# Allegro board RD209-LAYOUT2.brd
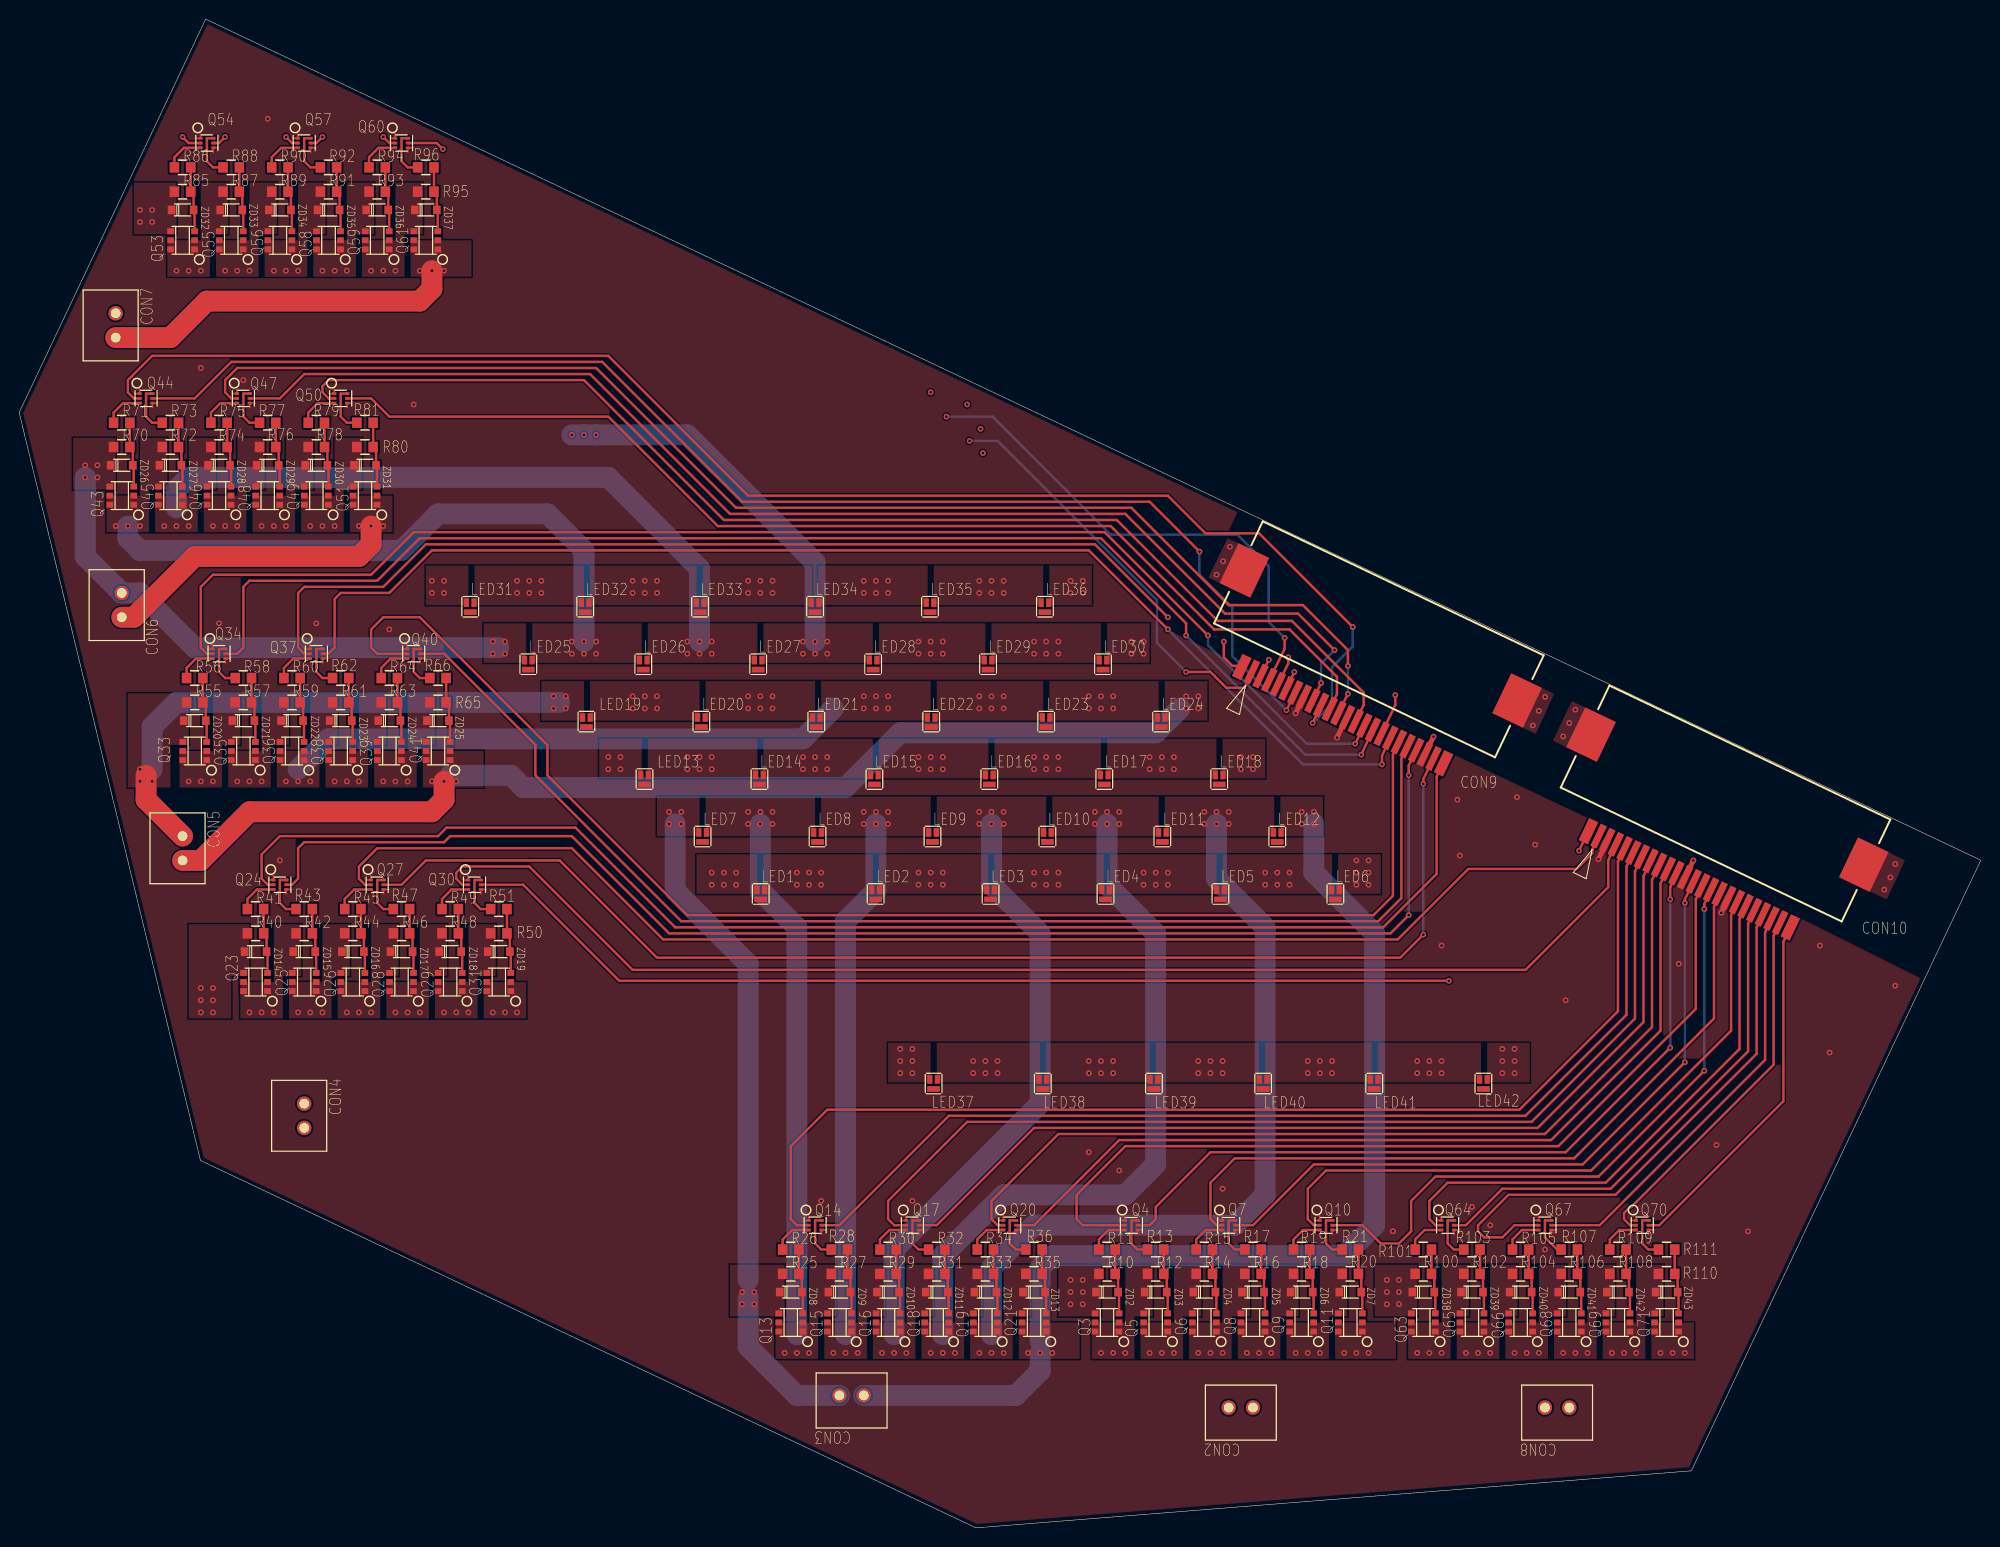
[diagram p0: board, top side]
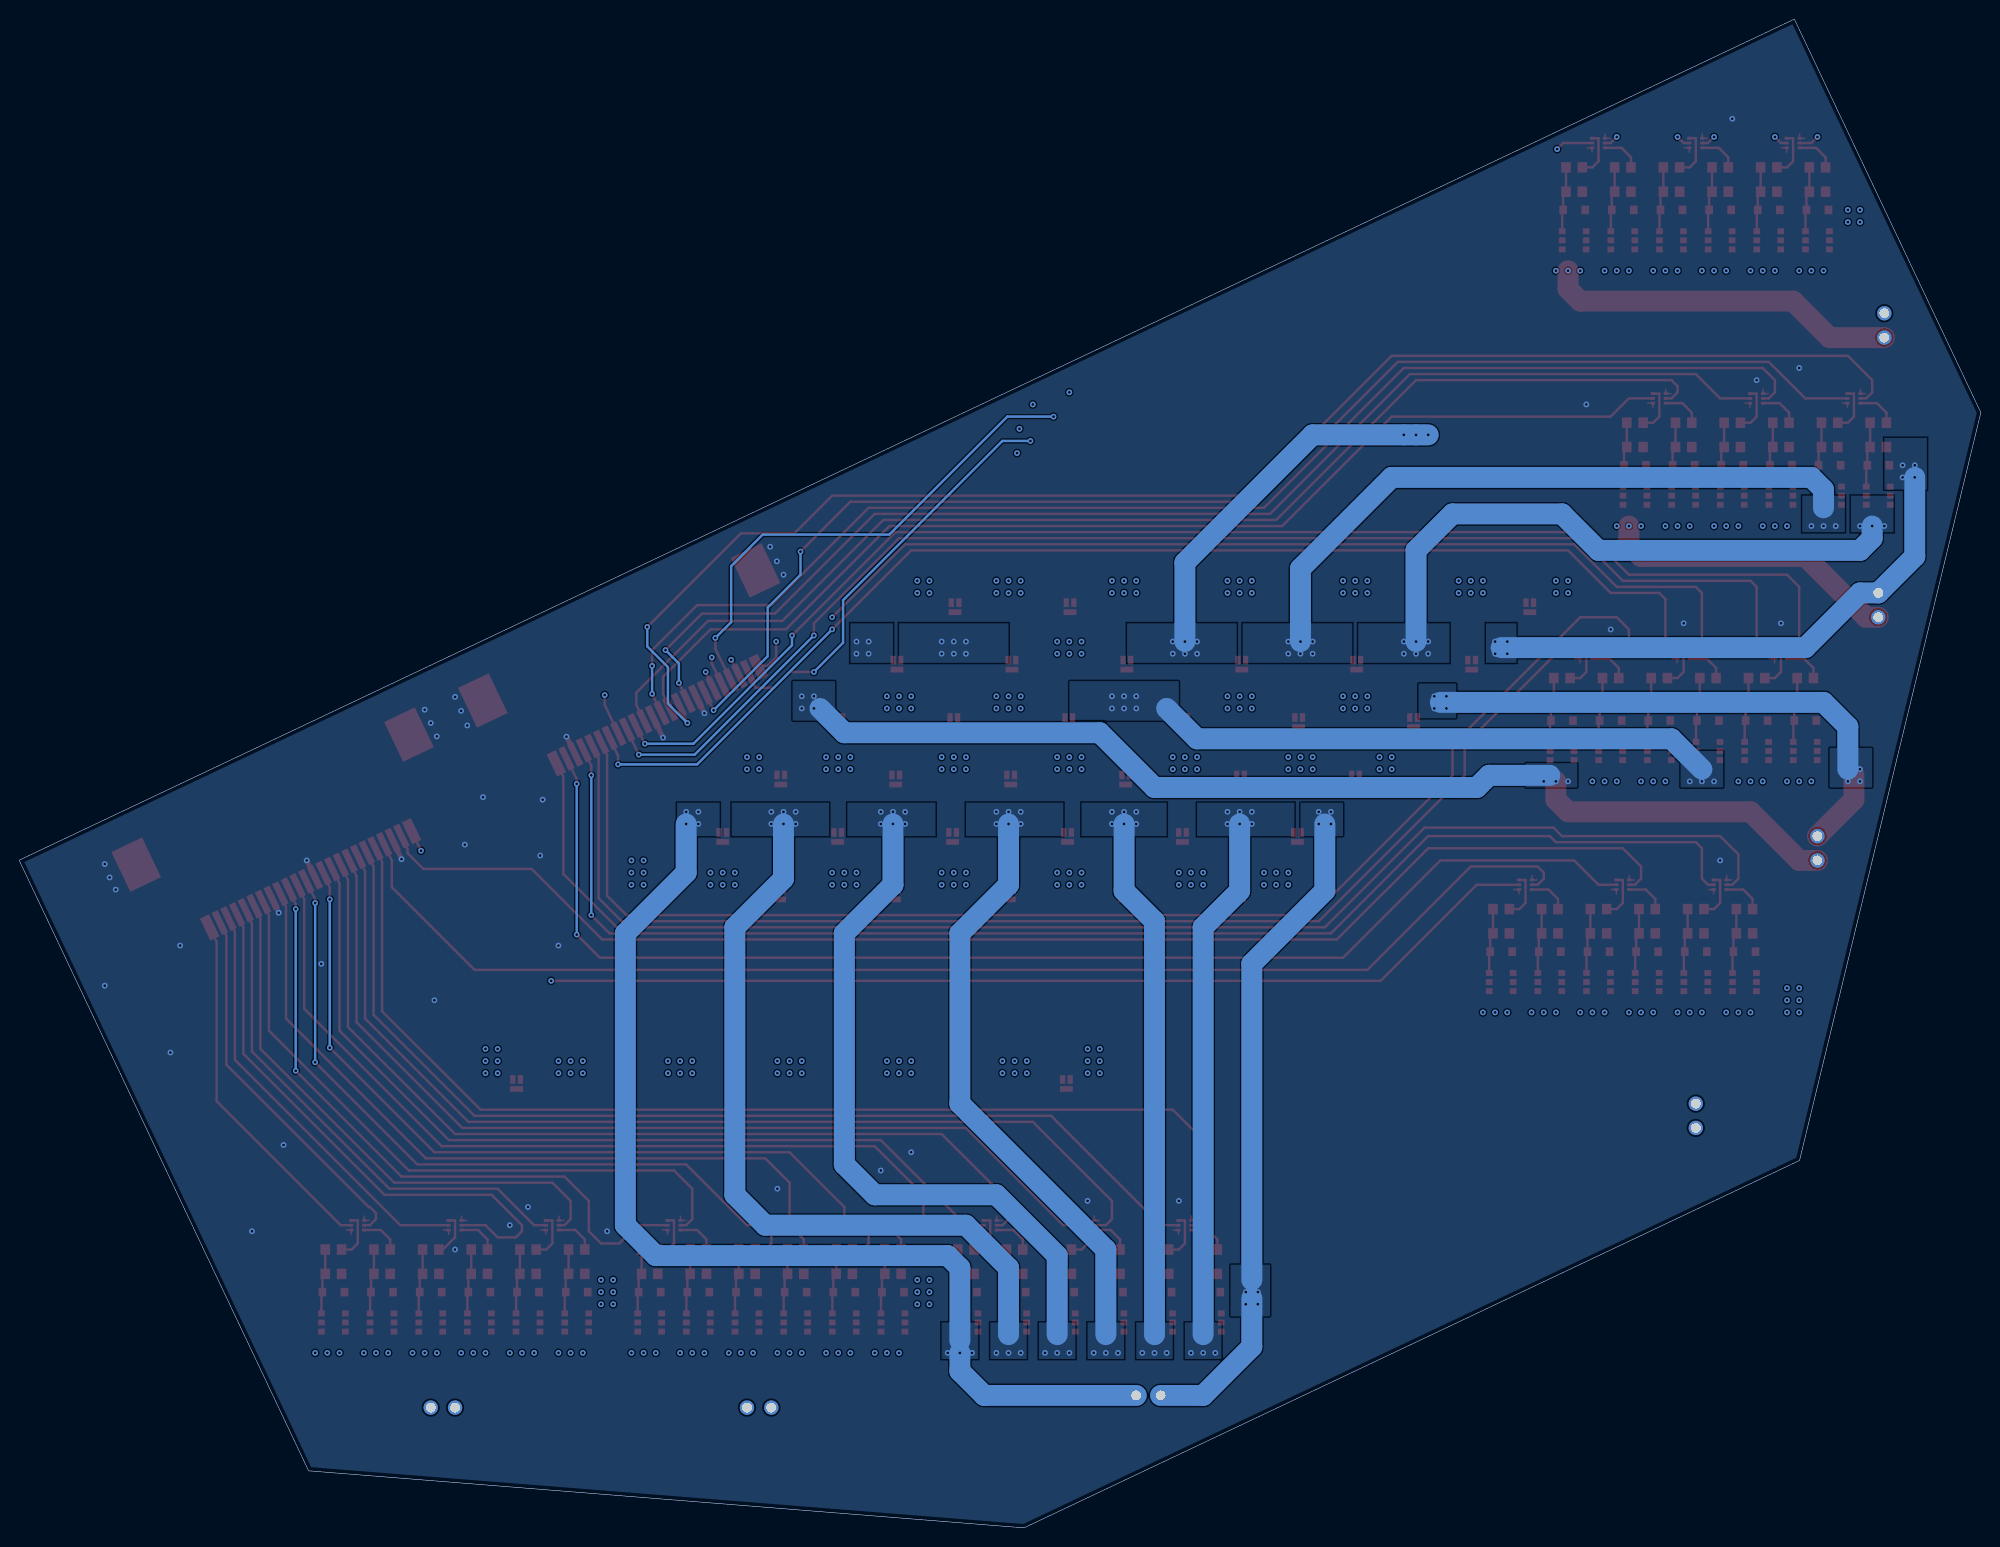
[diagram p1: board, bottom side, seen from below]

Outline 204.81 x 157.58 mm; copper layers: TOP, CONDUCTIVE2, CONDUCTIVE3, BOTTOM. Coordinates in mm from the lower left corner of the outline.
Outline path: 0,116.49 19.47,157.58 204.81,69.73 174.59,5.96 99.89,0 18.93,38.37 0,116.49

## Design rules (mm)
constraint set DEFAULT: 

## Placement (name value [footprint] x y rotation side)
CON2  -  [B2B_XH_A]  127.55 12.56 180 top
CON3  -  [B2B_XH_A]  86.91 13.83 180 top
CON4  -  [B2B_XH_A]  29.76 43.04 90 top
CON5  -  [B2B_XH_A]  17.06 70.98 90 top
CON6  -  [B2B_XH_A]  10.71 96.38 90 top
CON7  -  [B2B_XH_A]  10.07 125.59 90 top
CON8  -  [B2B_XH_A]  160.57 12.56 180 top
CON9  -  [WB01230AKP]  142.16 93.2 334.5 top
CON10  -  [WB01230AKP]  178.35 76.06 334.5 top
LED1  -  [KW]  77.42 66.21 0 top
LED2  -  [KW]  89.42 66.21 0 top
LED3  -  [KW]  101.42 66.21 0 top
LED4  -  [KW]  113.42 66.21 0 top
LED5  -  [KW]  125.42 66.21 0 top
LED6  -  [KW]  137.42 66.21 0 top
LED7  -  [KW]  71.35 72.21 0 top
LED8  -  [KW]  83.35 72.21 0 top
LED9  -  [KW]  95.35 72.21 0 top
LED10  -  [KW]  107.35 72.21 0 top
LED11  -  [KW]  119.35 72.21 0 top
LED12  -  [KW]  131.35 72.21 0 top
LED13  -  [KW]  65.29 78.21 0 top
LED14  -  [KW]  77.29 78.21 0 top
LED15  -  [KW]  89.29 78.21 0 top
LED16  -  [KW]  101.29 78.21 0 top
LED17  -  [KW]  113.29 78.21 0 top
LED18  -  [KW]  125.29 78.21 0 top
LED19  -  [KW]  59.22 84.21 0 top
LED20  -  [KW]  71.22 84.21 0 top
LED21  -  [KW]  83.22 84.21 0 top
LED22  -  [KW]  95.22 84.21 0 top
LED23  -  [KW]  107.22 84.21 0 top
LED24  -  [KW]  119.22 84.21 0 top
LED25  -  [KW]  53.16 90.21 0 top
LED26  -  [KW]  65.16 90.21 0 top
LED27  -  [KW]  77.16 90.21 0 top
LED28  -  [KW]  89.16 90.21 0 top
LED29  -  [KW]  101.16 90.21 0 top
LED30  -  [KW]  113.16 90.21 0 top
LED31  -  [KW]  47.09 96.21 0 top
LED32  -  [KW]  59.09 96.21 0 top
LED33  -  [KW]  71.09 96.21 0 top
LED34  -  [KW]  83.09 96.21 0 top
LED35  -  [KW]  95.09 96.21 0 top
LED36  -  [KW]  107.09 96.21 0 top
LED37  -  [KW]  95.47 46.41 0 top
LED38  -  [KW]  106.88 46.41 0 top
LED39  -  [KW]  118.47 46.41 0 top
LED40  -  [KW]  129.88 46.41 0 top
LED41  -  [KW]  141.47 46.41 0 top
LED42  -  [KW]  152.88 46.41 0 top
Q3  -  [TSOP6F]  113.58 21.45 90 top
Q4  -  [ES6]  116.12 31.61 270 top
Q5  -  [TSOP6F]  118.66 21.45 90 top
Q6  -  [TSOP6F]  123.74 21.45 90 top
Q7  -  [ES6]  126.28 31.61 270 top
Q8  -  [TSOP6F]  128.82 21.45 90 top
Q9  -  [TSOP6F]  133.9 21.45 90 top
Q10  -  [ES6]  136.44 31.61 270 top
Q11  -  [TSOP6F]  138.98 21.45 90 top
Q13  -  [TSOP6F]  80.56 21.45 90 top
Q14  -  [ES6]  83.1 31.61 270 top
Q15  -  [TSOP6F]  85.64 21.45 90 top
Q16  -  [TSOP6F]  90.72 21.45 90 top
Q17  -  [ES6]  93.26 31.61 270 top
Q18  -  [TSOP6F]  95.8 21.45 90 top
Q19  -  [TSOP6F]  100.88 21.45 90 top
Q20  -  [ES6]  103.42 31.61 270 top
Q21  -  [TSOP6F]  105.96 21.45 90 top
Q23  -  [TSOP6F]  24.68 57.01 90 top
Q24  -  [ES6]  27.22 67.17 270 top
Q25  -  [TSOP6F]  29.76 57.01 90 top
Q26  -  [TSOP6F]  34.84 57.01 90 top
Q27  -  [ES6]  37.38 67.17 270 top
Q28  -  [TSOP6F]  39.92 57.01 90 top
Q29  -  [TSOP6F]  45 57.01 90 top
Q30  -  [ES6]  47.54 67.17 270 top
Q31  -  [TSOP6F]  50.08 57.01 90 top
Q33  -  [TSOP6F]  18.33 81.14 90 top
Q34  -  [ES6]  20.87 91.3 270 top
Q35  -  [TSOP6F]  23.41 81.14 90 top
Q36  -  [TSOP6F]  28.49 81.14 90 top
Q37  -  [ES6]  31.03 91.3 270 top
Q38  -  [TSOP6F]  33.57 81.14 90 top
Q39  -  [TSOP6F]  38.65 81.14 90 top
Q40  -  [ES6]  41.19 91.3 270 top
Q41  -  [TSOP6F]  43.73 81.14 90 top
Q43  -  [TSOP6F]  10.71 107.81 90 top
Q44  -  [ES6]  13.25 117.97 270 top
Q45  -  [TSOP6F]  15.79 107.81 90 top
Q46  -  [TSOP6F]  20.87 107.81 90 top
Q47  -  [ES6]  23.41 117.97 270 top
Q48  -  [TSOP6F]  25.95 107.81 90 top
Q49  -  [TSOP6F]  31.03 107.81 90 top
Q50  -  [ES6]  33.57 117.97 270 top
Q51  -  [TSOP6F]  36.11 107.81 90 top
Q53  -  [TSOP6F]  17.06 134.48 90 top
Q54  -  [ES6]  19.6 144.64 270 top
Q55  -  [TSOP6F]  22.14 134.48 90 top
Q56  -  [TSOP6F]  27.22 134.48 90 top
Q57  -  [ES6]  29.76 144.64 270 top
Q58  -  [TSOP6F]  32.3 134.48 90 top
Q59  -  [TSOP6F]  37.38 134.48 90 top
Q60  -  [ES6]  39.92 144.64 270 top
Q61  -  [TSOP6F]  42.46 134.48 90 top
Q63  -  [TSOP6F]  146.6 21.45 90 top
Q64  -  [ES6]  149.14 31.61 270 top
Q65  -  [TSOP6F]  151.68 21.45 90 top
Q66  -  [TSOP6F]  156.76 21.45 90 top
Q67  -  [ES6]  159.3 31.61 270 top
Q68  -  [TSOP6F]  161.84 21.45 90 top
Q69  -  [TSOP6F]  166.92 21.45 90 top
Q70  -  [ES6]  169.46 31.61 270 top
Q71  -  [TSOP6F]  172 21.45 90 top
R10  -  [R0603]  113.58 26.53 180 top
R11  -  [R0603]  113.58 29.07 180 top
R12  -  [R0603]  118.66 26.53 180 top
R13  -  [R0603]  118.66 29.07 180 top
R14  -  [R0603]  123.74 26.53 180 top
R15  -  [R0603]  123.74 29.07 180 top
R16  -  [R0603]  128.82 26.53 180 top
R17  -  [R0603]  128.82 29.07 180 top
R18  -  [R0603]  133.9 26.53 180 top
R19  -  [R0603]  133.9 29.07 180 top
R20  -  [R0603]  138.98 26.53 180 top
R21  -  [R0603]  138.98 29.07 180 top
R25  -  [R0603]  80.56 26.53 180 top
R26  -  [R0603]  80.56 29.07 180 top
R27  -  [R0603]  85.64 26.53 180 top
R28  -  [R0603]  85.64 29.07 180 top
R29  -  [R0603]  90.72 26.53 180 top
R30  -  [R0603]  90.72 29.07 180 top
R31  -  [R0603]  95.8 26.53 180 top
R32  -  [R0603]  95.8 29.07 180 top
R33  -  [R0603]  100.88 26.53 180 top
R34  -  [R0603]  100.88 29.07 180 top
R35  -  [R0603]  105.96 26.53 180 top
R36  -  [R0603]  105.96 29.07 180 top
R40  -  [R0603]  24.68 62.09 180 top
R41  -  [R0603]  24.68 64.63 180 top
R42  -  [R0603]  29.76 62.09 180 top
R43  -  [R0603]  29.76 64.63 180 top
R44  -  [R0603]  34.84 62.09 180 top
R45  -  [R0603]  34.84 64.63 180 top
R46  -  [R0603]  39.92 62.09 180 top
R47  -  [R0603]  39.92 64.63 180 top
R48  -  [R0603]  45 62.09 180 top
R49  -  [R0603]  45 64.63 180 top
R50  -  [R0603]  50.08 62.09 180 top
R51  -  [R0603]  50.08 64.63 180 top
R55  -  [R0603]  18.33 86.22 180 top
R56  -  [R0603]  18.33 88.76 180 top
R57  -  [R0603]  23.41 86.22 180 top
R58  -  [R0603]  23.41 88.76 180 top
R59  -  [R0603]  28.49 86.22 180 top
R60  -  [R0603]  28.49 88.76 180 top
R61  -  [R0603]  33.57 86.22 180 top
R62  -  [R0603]  33.57 88.76 180 top
R63  -  [R0603]  38.65 86.22 180 top
R64  -  [R0603]  38.65 88.76 180 top
R65  -  [R0603]  43.73 86.22 180 top
R66  -  [R0603]  43.73 88.76 180 top
R70  -  [R0603]  10.71 112.89 180 top
R71  -  [R0603]  10.71 115.43 180 top
R72  -  [R0603]  15.79 112.89 180 top
R73  -  [R0603]  15.79 115.43 180 top
R74  -  [R0603]  20.87 112.89 180 top
R75  -  [R0603]  20.87 115.43 180 top
R76  -  [R0603]  25.95 112.89 180 top
R77  -  [R0603]  25.95 115.43 180 top
R78  -  [R0603]  31.03 112.89 180 top
R79  -  [R0603]  31.03 115.43 180 top
R80  -  [R0603]  36.11 112.89 180 top
R81  -  [R0603]  36.11 115.43 180 top
R85  -  [R0603]  17.06 139.56 180 top
R86  -  [R0603]  17.06 142.1 180 top
R87  -  [R0603]  22.14 139.56 180 top
R88  -  [R0603]  22.14 142.1 180 top
R89  -  [R0603]  27.22 139.56 180 top
R90  -  [R0603]  27.22 142.1 180 top
R91  -  [R0603]  32.3 139.56 180 top
R92  -  [R0603]  32.3 142.1 180 top
R93  -  [R0603]  37.38 139.56 180 top
R94  -  [R0603]  37.38 142.1 180 top
R95  -  [R0603]  42.46 139.56 180 top
R96  -  [R0603]  42.46 142.1 180 top
R100  -  [R0603]  146.6 26.53 180 top
R101  -  [R0603]  146.6 29.07 180 top
R102  -  [R0603]  151.68 26.53 180 top
R103  -  [R0603]  151.68 29.07 180 top
R104  -  [R0603]  156.76 26.53 180 top
R105  -  [R0603]  156.76 29.07 180 top
R106  -  [R0603]  161.84 26.53 180 top
R107  -  [R0603]  161.84 29.07 180 top
R108  -  [R0603]  166.92 26.53 180 top
R109  -  [R0603]  166.92 29.07 180 top
R110  -  [R0603]  172 26.53 180 top
R111  -  [R0603]  172 29.07 180 top
ZD2  -  [USC]  113.58 24.62 0 top
ZD3  -  [USC]  118.66 24.62 0 top
ZD4  -  [USC]  123.74 24.62 0 top
ZD5  -  [USC]  128.82 24.62 0 top
ZD6  -  [USC]  133.9 24.62 0 top
ZD7  -  [USC]  138.98 24.62 0 top
ZD8  -  [USC]  80.56 24.62 0 top
ZD9  -  [USC]  85.64 24.62 0 top
ZD10  -  [USC]  90.72 24.62 0 top
ZD11  -  [USC]  95.8 24.62 0 top
ZD12  -  [USC]  100.88 24.62 0 top
ZD13  -  [USC]  105.96 24.62 0 top
ZD14  -  [USC]  24.68 60.19 0 top
ZD15  -  [USC]  29.76 60.19 0 top
ZD16  -  [USC]  34.84 60.19 0 top
ZD17  -  [USC]  39.92 60.19 0 top
ZD18  -  [USC]  45 60.19 0 top
ZD19  -  [USC]  50.08 60.19 0 top
ZD20  -  [USC]  18.33 84.31 0 top
ZD21  -  [USC]  23.41 84.31 0 top
ZD22  -  [USC]  28.49 84.31 0 top
ZD23  -  [USC]  33.57 84.31 0 top
ZD24  -  [USC]  38.65 84.31 0 top
ZD25  -  [USC]  43.73 84.31 0 top
ZD26  -  [USC]  10.71 110.98 0 top
ZD27  -  [USC]  15.79 110.98 0 top
ZD28  -  [USC]  20.87 110.98 0 top
ZD29  -  [USC]  25.95 110.98 0 top
ZD30  -  [USC]  31.03 110.98 0 top
ZD31  -  [USC]  36.11 110.98 0 top
ZD32  -  [USC]  17.06 137.66 0 top
ZD33  -  [USC]  22.14 137.66 0 top
ZD34  -  [USC]  27.22 137.66 0 top
ZD35  -  [USC]  32.3 137.66 0 top
ZD36  -  [USC]  37.38 137.66 0 top
ZD37  -  [USC]  42.46 137.66 0 top
ZD38  -  [USC]  146.6 24.62 0 top
ZD39  -  [USC]  151.68 24.62 0 top
ZD40  -  [USC]  156.76 24.62 0 top
ZD41  -  [USC]  161.84 24.62 0 top
ZD42  -  [USC]  166.92 24.62 0 top
ZD43  -  [USC]  172 24.62 0 top

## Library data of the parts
CON2-CON8 = B2B-XH-A: alternate symbols: (T:B2B_XH_A;B:B2B_XH_A_bk)
CON9 CON10 = GAS220000030: alternate symbols: (T:WB01230AKP,CON10_WB01230AKP;B:WB01230BKP)
LED1-LED42 = KW: alternate symbols: (T:KW;B:KW_bk)
Q3 Q5 Q6 Q8 Q9 Q11 Q13 Q15 Q16 Q18 Q19 Q21 Q23 Q25 Q26 Q28 Q29 Q31 Q33 Q35 Q36 Q38 Q39 Q41 Q43 Q45 Q46 Q48 Q49 Q51 Q53 Q55 Q56 Q58 Q59 Q61 Q63 Q65 Q66 Q68 Q69 Q71 = TSOP6F: alternate symbols: (T:TSOP6F;B:TSOP6F_bk)
Q4 Q7 Q10 Q14 Q17 Q20 Q24 Q27 Q30 Q34 Q37 Q40 Q44 Q47 Q50 Q54 Q57 Q60 Q64 Q67 Q70 = ES6: alternate symbols: (T:ES6;B:ES6_bk)
R10 R12 R14-R16 R18 R25 R27 R29-R31 R33 R40 R42 R44-R46 R48 R55 R57 R59-R61 R63 R70 R72 R74-R76 R78 R85 R87 R89-R91 R93 R100 R102 R104-R106 R108 = R0603_9: alternate symbols: (T:R0603;B:R0603_bk)
R11 R13 R20 R26 R28 R35 R41 R43 R50 R56 R58 R65 R71 R73 R80 R86 R88 R95 R101 R103 R110 = R0603_2: alternate symbols: (T:R0603;B:R0603_bk)
R17 R32 R47 R62 R77 R92 R107 = R0603_5: alternate symbols: (T:R0603;B:R0603_bk)
R19 R34 R49 R64 R79 R94 R109 = R0603_1: alternate symbols: (T:R0603;B:R0603_bk)
R21 R36 R51 R66 R81 R96 R111 = R0603_8: alternate symbols: (T:R0603;B:R0603_bk)
ZD2-ZD43 = USC: alternate symbols: (T:USC;B:USC_bk)

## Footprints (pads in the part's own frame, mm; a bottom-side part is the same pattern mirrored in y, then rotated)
B2B_XH_A
  round 1.5 hole 1: 1(-1.27,0) 2(1.27,0)
ES6
  rect 0.3x0.45 smd: 1(-0.5,-0.675) 2(0,-0.675) 3(0.5,-0.675) 4(0.5,0.675) 5(0,0.675) 6(-0.5,0.675)
KW
  rect 0.55x0.9 smd: A(-0.398,0.425) C(0.398,0.425)
  rect 1.34x0.6 smd: P_3(0,-0.57)
R0603
  rect 1x1.1 smd: 1(-0.85,0) 2(0.85,0)
TSOP6F
  rect 0.62x0.7 smd: 1(-0.95,-1.25) 2(0,-1.25) 3(0.95,-1.25) 4(0.95,1.25) 5(0,1.25) 6(-0.95,1.25)
USC
  rect 0.8x0.9 smd: A(1.15,0) K(-1.15,0)
WB01230AKP
  rect 0.7x2.55 smd: 1(-10.5,-9.225) 2(-8.5,-9.225) 3(-6.5,-9.225) 4(-4.5,-9.225) 5(-2.5,-9.225) 6(-0.5,-9.225) 7(1.5,-9.225) 8(3.5,-9.225) 9(5.5,-9.225) 10(7.5,-9.225) 11(9.5,-9.225) 14(-9.5,-9.225) 15(-7.5,-9.225) 16(-5.5,-9.225) 17(-3.5,-9.225) 18(-1.5,-9.225) 19(0.5,-9.225) 20(2.5,-9.225) 21(4.5,-9.225) 22(6.5,-9.225) 23(8.5,-9.225) 24(10.5,-9.225)
  rect 3.55x4.6 smd: 1T(-15.775,0) 2T(15.775,0)
  rect 1.05x2.55 smd: 12(11.675,-9.225) 13(-11.675,-9.225)

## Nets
GND: CON9.1T CON9.2T CON9.4 CON9.11 CON9.19 CON10.1T CON10.2T CON10.6 CON10.14 CON10.21 Q4.1 Q4.4 Q7.1 Q7.4 Q10.1 Q10.4 Q14.1 Q14.4 Q17.1 Q17.4 Q20.1 Q20.4 Q24.1 Q24.4 Q27.1 Q27.4 Q30.1 Q30.4 Q34.1 Q34.4 Q37.1 Q37.4 Q40.1 Q40.4 Q44.1 Q44.4 Q47.1 Q47.4 Q50.1 Q50.4 Q54.1 Q54.4 Q57.1 Q57.4 Q60.1 Q60.4 Q64.1 Q64.4 Q67.1 Q67.4 Q70.1 Q70.4
LED1: CON10.18 Q4.5
LED2: CON10.7 Q4.2
LED3: CON10.19 Q7.5
LED4: CON10.8 Q7.2
LED5: CON10.20 Q10.5
LED6: CON10.9 Q10.2
LED7: CON10.3 Q14.5
LED8: CON10.15 Q14.2
LED9: CON10.4 Q17.5
LED10: CON10.16 Q17.2
LED11: CON10.5 Q20.5
LED12: CON10.17 Q20.2
LED13: CON9.23 Q24.5
LED14: CON9.12 Q24.2
LED15: CON9.24 Q27.5
LED16: CON10.1 Q27.2
LED17: CON10.13 Q30.5
LED18: CON10.2 Q30.2
LED19: CON9.8 Q34.5
LED20: CON9.20 Q34.2
LED21: CON9.9 Q37.5
LED22: CON9.21 Q37.2
LED23: CON9.10 Q40.5
LED24: CON9.22 Q40.2
LED25: CON9.16 Q44.5
LED26: CON9.5 Q44.2
LED27: CON9.17 Q47.5
LED28: CON9.6 Q47.2
LED29: CON9.18 Q50.5
LED30: CON9.7 Q50.2
LED31: CON9.1 Q54.5
LED32: CON9.13 Q54.2
LED33: CON9.2 Q57.5
LED34: CON9.14 Q57.2
LED35: CON9.3 Q60.5
LED36: CON9.15 Q60.2
LED37: CON10.10 Q64.5
LED38: CON10.22 Q64.2
LED39: CON10.11 Q67.5
LED40: CON10.23 Q67.2
LED41: CON10.12 Q70.5
LED42: CON10.24 Q70.2
LED+1: CON2.2 LED1.A Q3.4 R10.2 ZD2.K
LED+2: CON3.2 LED7.A Q13.4 R25.2 ZD8.K
LED+3: CON4.2 LED13.A Q23.4 R40.2 ZD14.K
LED+4: CON5.2 LED19.A Q33.4 R55.2 ZD20.K
LED+5: CON6.2 LED25.A Q43.4 R70.2 ZD26.K
LED+6: CON7.2 LED31.A Q53.4 R85.2 ZD32.K
LED+7: CON8.2 LED37.A Q63.4 R100.2 ZD38.K
LED-1: CON2.1 LED6.C Q11.1 Q11.2 Q11.5 Q11.6
LED-2: CON3.1 LED12.C Q21.1 Q21.2 Q21.5 Q21.6
LED-3: CON4.1 LED18.C Q31.1 Q31.2 Q31.5 Q31.6
LED-4: CON5.1 LED24.C Q41.1 Q41.2 Q41.5 Q41.6
LED-5: CON6.1 LED30.C Q51.1 Q51.2 Q51.5 Q51.6
LED-6: CON7.1 LED36.C Q61.1 Q61.2 Q61.5 Q61.6
LED-7: CON8.1 LED42.C Q71.1 Q71.2 Q71.5 Q71.6
N_1: Q4.6 Q5.3 R12.1 R13.1 R13.2 ZD3.A
N_2: Q3.3 Q4.3 R10.1 R11.1 R11.2 ZD2.A
N_3: Q6.3 Q7.3 R14.1 R15.1 R15.2 ZD4.A
N_4: Q7.6 Q8.3 R16.1 R17.1 R17.2 ZD5.A
N_5: Q9.3 Q10.3 R18.1 R19.1 R19.2 ZD6.A
N_6: Q10.6 Q11.3 R20.1 R21.1 R21.2 ZD7.A
N_7: Q13.3 Q14.3 R25.1 R26.1 R26.2 ZD8.A
N_8: Q14.6 Q15.3 R27.1 R28.1 R28.2 ZD9.A
N_9: Q16.3 Q17.3 R29.1 R30.1 R30.2 ZD10.A
N_10: Q17.6 Q18.3 R31.1 R32.1 R32.2 ZD11.A
N_11: Q19.3 Q20.3 R33.1 R34.1 R34.2 ZD12.A
N_12: Q20.6 Q21.3 R35.1 R36.1 R36.2 ZD13.A
N_13: Q23.3 Q24.3 R40.1 R41.1 R41.2 ZD14.A
N_15: Q24.6 Q25.3 R42.1 R43.1 R43.2 ZD15.A
N_16: LED1.C LED2.A Q3.1 Q3.2 Q3.5 Q3.6 Q5.4 R12.2 ZD3.K
N_18: Q26.3 Q27.3 R44.1 R45.1 R45.2 ZD16.A
N_20: LED2.C LED3.A Q5.1 Q5.2 Q5.5 Q5.6 Q6.4 R14.2 ZD4.K
N_22: Q27.6 Q28.3 R46.1 R47.1 R47.2 ZD17.A
N_23: LED3.C LED4.A Q6.1 Q6.2 Q6.5 Q6.6 Q8.4 R16.2 ZD5.K
N_25: Q29.3 Q30.3 R48.1 R49.1 R49.2 ZD18.A
N_26: LED4.C LED5.A Q8.1 Q8.2 Q8.5 Q8.6 Q9.4 R18.2 ZD6.K
N_28: Q30.6 Q31.3 R50.1 R51.1 R51.2 ZD19.A
N_29: LED7.C LED8.A Q13.1 Q13.2 Q13.5 Q13.6 Q15.4 R27.2 ZD9.K
N_30: LED5.C LED6.A Q9.1 Q9.2 Q9.5 Q9.6 Q11.4 R20.2 ZD7.K
N_32: Q33.3 Q34.3 R55.1 R56.1 R56.2 ZD20.A
N_33: Q34.6 Q35.3 R57.1 R58.1 R58.2 ZD21.A
N_35: Q36.3 Q37.3 R59.1 R60.1 R60.2 ZD22.A
N_36: Q37.6 Q38.3 R61.1 R62.1 R62.2 ZD23.A
N_38: Q39.3 Q40.3 R63.1 R64.1 R64.2 ZD24.A
N_39: LED8.C LED9.A Q15.1 Q15.2 Q15.5 Q15.6 Q16.4 R29.2 ZD10.K
N_41: Q40.6 Q41.3 R65.1 R66.1 R66.2 ZD25.A
N_42: LED9.C LED10.A Q16.1 Q16.2 Q16.5 Q16.6 Q18.4 R31.2 ZD11.K
N_44: Q43.3 Q44.3 R70.1 R71.1 R71.2 ZD26.A
N_45: LED10.C LED11.A Q18.1 Q18.2 Q18.5 Q18.6 Q19.4 R33.2 ZD12.K
N_47: Q44.6 Q45.3 R72.1 R73.1 R73.2 ZD27.A
N_48: LED11.C LED12.A Q19.1 Q19.2 Q19.5 Q19.6 Q21.4 R35.2 ZD13.K
N_50: Q46.3 Q47.3 R74.1 R75.1 R75.2 ZD28.A
N_51: Q47.6 Q48.3 R76.1 R77.1 R77.2 ZD29.A
N_53: Q49.3 Q50.3 R78.1 R79.1 R79.2 ZD30.A
N_54: Q50.6 Q51.3 R80.1 R81.1 R81.2 ZD31.A
N_55: Q53.3 Q54.3 R85.1 R86.1 R86.2 ZD32.A
N_57: LED13.C LED14.A Q23.1 Q23.2 Q23.5 Q23.6 Q25.4 R42.2 ZD15.K
N_59: Q54.6 Q55.3 R87.1 R88.1 R88.2 ZD33.A
N_60: LED14.C LED15.A Q25.1 Q25.2 Q25.5 Q25.6 Q26.4 R44.2 ZD16.K
N_62: Q56.3 Q57.3 R89.1 R90.1 R90.2 ZD34.A
N_63: LED15.C LED16.A Q26.1 Q26.2 Q26.5 Q26.6 Q28.4 R46.2 ZD17.K
N_65: Q57.6 Q58.3 R91.1 R92.1 R92.2 ZD35.A
N_66: LED16.C LED17.A Q28.1 Q28.2 Q28.5 Q28.6 Q29.4 R48.2 ZD18.K
N_68: Q59.3 Q60.3 R93.1 R94.1 R94.2 ZD36.A
N_69: LED17.C LED18.A Q29.1 Q29.2 Q29.5 Q29.6 Q31.4 R50.2 ZD19.K
N_71: Q60.6 Q61.3 R95.1 R96.1 R96.2 ZD37.A
N_72: Q63.3 Q64.3 R100.1 R101.1 R101.2 ZD38.A
N_74: Q64.6 Q65.3 R102.1 R103.1 R103.2 ZD39.A
N_75: Q66.3 Q67.3 R104.1 R105.1 R105.2 ZD40.A
N_76: Q67.6 Q68.3 R106.1 R107.1 R107.2 ZD41.A
N_77: Q69.3 Q70.3 R108.1 R109.1 R109.2 ZD42.A
N_78: LED19.C LED20.A Q33.1 Q33.2 Q33.5 Q33.6 Q35.4 R57.2 ZD21.K
N_80: Q70.6 Q71.3 R110.1 R111.1 R111.2 ZD43.A
N_81: LED20.C LED21.A Q35.1 Q35.2 Q35.5 Q35.6 Q36.4 R59.2 ZD22.K
N_84: LED21.C LED22.A Q36.1 Q36.2 Q36.5 Q36.6 Q38.4 R61.2 ZD23.K
N_87: LED22.C LED23.A Q38.1 Q38.2 Q38.5 Q38.6 Q39.4 R63.2 ZD24.K
N_90: LED23.C LED24.A Q39.1 Q39.2 Q39.5 Q39.6 Q41.4 R65.2 ZD25.K
N_99: LED25.C LED26.A Q43.1 Q43.2 Q43.5 Q43.6 Q45.4 R72.2 ZD27.K
N_102: LED26.C LED27.A Q45.1 Q45.2 Q45.5 Q45.6 Q46.4 R74.2 ZD28.K
N_105: LED27.C LED28.A Q46.1 Q46.2 Q46.5 Q46.6 Q48.4 R76.2 ZD29.K
N_108: LED28.C LED29.A Q48.1 Q48.2 Q48.5 Q48.6 Q49.4 R78.2 ZD30.K
N_111: LED29.C LED30.A Q49.1 Q49.2 Q49.5 Q49.6 Q51.4 R80.2 ZD31.K
N_120: LED31.C LED32.A Q53.1 Q53.2 Q53.5 Q53.6 Q55.4 R87.2 ZD33.K
N_123: LED32.C LED33.A Q55.1 Q55.2 Q55.5 Q55.6 Q56.4 R89.2 ZD34.K
N_126: LED33.C LED34.A Q56.1 Q56.2 Q56.5 Q56.6 Q58.4 R91.2 ZD35.K
N_129: LED34.C LED35.A Q58.1 Q58.2 Q58.5 Q58.6 Q59.4 R93.2 ZD36.K
N_132: LED35.C LED36.A Q59.1 Q59.2 Q59.5 Q59.6 Q61.4 R95.2 ZD37.K
N_141: LED37.C LED38.A Q63.1 Q63.2 Q63.5 Q63.6 Q65.4 R102.2 ZD39.K
N_144: LED38.C LED39.A Q65.1 Q65.2 Q65.5 Q65.6 Q66.4 R104.2 ZD40.K
N_147: LED39.C LED40.A Q66.1 Q66.2 Q66.5 Q66.6 Q68.4 R106.2 ZD41.K
N_150: LED40.C LED41.A Q68.1 Q68.2 Q68.5 Q68.6 Q69.4 R108.2 ZD42.K
N_153: LED41.C LED42.A Q69.1 Q69.2 Q69.5 Q69.6 Q71.4 R110.2 ZD43.K

Pads without a net: LED1 P_3; LED2 P_3; LED3 P_3; LED4 P_3; LED5 P_3; LED6 P_3; LED7 P_3; LED8 P_3; LED9 P_3; LED10 P_3; LED11 P_3; LED12 P_3; LED13 P_3; LED14 P_3; LED15 P_3; LED16 P_3; LED17 P_3; LED18 P_3; LED19 P_3; LED20 P_3; LED21 P_3; LED22 P_3; LED23 P_3; LED24 P_3; LED25 P_3; LED26 P_3; LED27 P_3; LED28 P_3; LED29 P_3; LED30 P_3; LED31 P_3; LED32 P_3; LED33 P_3; LED34 P_3; LED35 P_3; LED36 P_3; LED37 P_3; LED38 P_3; LED39 P_3; LED40 P_3; LED41 P_3; LED42 P_3

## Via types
v1: diameter 0.6, hole 0.3, TOP to BOTTOM, 529 vias

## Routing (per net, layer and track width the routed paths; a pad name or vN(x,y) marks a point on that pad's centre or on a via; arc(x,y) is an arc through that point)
GND: length 53.6
  TOP w0.15: 135.76,32.56 Q10.1 135.23,32.11 ; 28.56,145.14 29.08,145.14 29.08,145.59 ; 24.61,117.47 Q47.4 24.08,117.02 ; 150.34,31.11 Q64.4 149.81,30.66 ; 117.33,31.11 116.8,31.11 116.8,30.66 ; 30.36,92.25 Q37.1 29.82,91.8 ; 20.27,143.69 Q54.4 20.8,144.14 ; 127.48,31.11 Q7.4 126.95,30.66 ; 20.2,92.25 Q34.1 19.66,91.8 ; 27.89,66.22 Q24.4 28.43,66.67 ; 32.89,118.92 Q50.1 32.36,118.47 ; 102.74,32.56 102.74,32.11 102.22,32.11 ; 46.33,67.67 46.86,67.67 46.86,68.12 ; 22.21,118.47 Q47.1 22.73,118.92 ; 39.25,145.59 Q60.1 38.72,145.14 ; 94.47,31.11 93.94,31.11 93.94,30.66 ; 38.58,66.67 38.06,66.67 38.06,66.22 ; 12.57,118.92 Q44.1 12.05,118.47 ; 18.39,145.14 Q54.1 18.93,145.59 ; 92.58,32.56 Q17.1 92.05,32.11 ; 168.78,32.56 Q70.1 168.25,32.11 ; 22.07,90.8 Q34.4 21.55,90.34 ; 115.44,32.56 Q4.1 114.91,32.11 ; 41.86,90.34 Q40.4 42.39,90.8 ; 148.47,32.56 Q64.1 147.94,32.11 ; 170.66,31.11 Q70.4 170.13,30.66 ; 160.5,31.11 Q67.4 159.97,30.66 ; 83.77,30.66 Q14.4 84.3,31.11 ; 48.75,66.67 Q30.4 48.22,66.22 ; 39.98,91.8 Q40.1 40.52,92.25 ; 32.23,90.8 Q37.4 31.71,90.34 ; 30.96,144.14 Q57.4 30.43,143.69 ; 104.09,30.66 Q20.4 104.62,31.11 ; 125.6,32.56 Q7.1 125.07,32.11 ; 34.78,117.47 Q50.4 34.25,117.02 ; 82.42,32.56 Q14.1 81.89,32.11 ; 13.93,117.02 Q44.4 14.46,117.47 ; 41.12,144.14 40.59,144.14 40.59,143.69 ; 36.17,67.67 Q27.1 36.7,68.12 ; 26.01,67.67 26.54,67.67 26.54,68.12 ; 158.62,32.56 Q67.1 158.09,32.11 ; 137.65,31.11 Q10.4 137.12,30.66
  TOP w0.508: CON9.4 v1(133.26,85.08) ; CON10.21 v1(177.72,64.25) ; CON9.11 v1(147.67,82.64) ; CON10.14 v1(164.89,69.84) ; CON10.6 v1(174.79,69.71) ; CON9.19 v1(137.58,82.54)
  vias: v1(18.96,121.14) v1(20.87,94.47) v1(23.41,119.88) v1(25.95,147.18) v1(27.22,69.71) v1(31.03,94.47) v1(38.65,93.84) v1(41.19,117.33) v1(83.73,34.15) v1(93.26,34.15) v1(111.67,39.23) v1(114.85,37.32) v1(125.01,99.55) v1(125.71,100.95) v1(125.65,35.42) v1(126.41,102.48) v1(143.42,30.98) v1(148.5,60.82) v1(150.16,76.06) v1(150.41,70.22) v1(151.68,33.52) v1(153.59,31.61) v1(156.38,76.31) v1(158.03,83.81) v1(158.28,71.36) v1(158.66,85.33) v1(159.3,86.79) v1(159.3,29.07) v1(161.2,82.66) v1(161.46,55.11) v1(161.84,84.06) v1(162.47,85.46) v1(173.27,58.91) v1(177.21,39.99) v1(180.51,30.98) v1(188,60.82) v1(189.02,49.64) v1(194.73,66.66) v1(195.37,67.93) v1(195.88,69.33) v1(195.88,56.63)
LED1: length 82.4
  TOP w0.254: v1(172.38,65.65) 172.38,66.92 CON10.18 ; v1(172.38,50.15) 161.46,39.23 124.38,39.23 118.66,33.52 118.66,32.24 118.02,31.61 116.8,31.61
  BOTTOM w0.254: v1(172.38,50.15) v1(172.38,65.65)
LED2: length 93.6
  TOP w0.254: Q4.2 111.04,31.61 110.41,32.24 110.41,34.78 115.48,39.87 160.7,39.87 175.05,54.22 175.05,65.65 CON10.7
LED3: length 73.1
  TOP w0.254: v1(173.91,65.27) 173.91,65.65 CON10.19 ; v1(173.91,48.63) 163.24,37.96 135.17,37.96 128.82,31.61 Q7.5
  BOTTOM w0.254: v1(173.91,48.63) v1(173.91,65.27)
LED4: length 78.1
  TOP w0.254: Q7.2 125.01,31.61 124.38,32.24 124.38,36.05 126.91,38.59 162.35,38.59 176.95,53.2 176.95,64.88 CON10.8
LED5: length 68
  TOP w0.254: Q10.5 140.25,31.61 142.16,29.71 144.06,29.71 145.33,30.98 145.33,34.15 147.87,36.69 164.89,36.69 v1(175.94,47.74) ; 176.63,66.66 175.94,65.14 v1(175.94,64.63)
  BOTTOM w0.254: v1(175.94,47.74) v1(175.94,64.63)
LED6: length 69.3
  TOP w0.254: Q10.2 135.17,31.61 134.53,32.24 134.53,35.42 136.44,37.32 164.13,37.32 178.73,51.93 178.73,63.99 CON10.9
LED7: length 110.2
  TOP w0.254: CON10.3 167.81,69.08 167.81,53.58 157.27,43.04 97.07,43.04 85.64,31.61 Q14.5
LED8: length 119.1
  TOP w0.254: CON10.15 166.92,69.58 166.92,53.96 156.63,43.68 84.37,43.68 80.56,39.87 80.56,32.24 81.19,31.61 Q14.2
LED9: length 101.4
  TOP w0.254: CON10.4 169.59,68.06 169.59,52.82 158.54,41.77 105.96,41.77 95.8,31.61 93.94,31.61
LED10: length 107
  TOP w0.254: Q17.2 91.35,31.61 90.72,32.24 90.72,34.15 98.97,42.41 157.9,42.41 168.7,53.2 168.7,68.57 CON10.16
LED11: length 92.7
  TOP w0.254: CON10.5 171.37,67.3 171.37,51.93 159.94,40.5 114.85,40.5 105.96,31.61 Q20.5
LED12: length 97
  TOP w0.254: 102.74,31.61 102.15,31.61 101.52,32.24 101.52,34.15 108.5,41.13 159.3,41.13 170.48,52.31 170.48,67.68 CON10.17
LED13: length 143.5
  TOP w0.254: v1(145.08,78.6) 145.08,79.62 CON9.23 ; Q24.5 28.49,67.17 29.13,67.8 29.13,70.98 29.76,71.61 44.36,71.61 45,72.25 57.7,72.25 67.86,62.09 143.17,62.09 v1(145.08,63.99)
  BOTTOM w0.254: v1(145.08,63.99) v1(145.08,78.6)
LED14: length 146.2
  TOP w0.254: CON9.12 148,78.47 148,68.31 142.41,62.73 68.49,62.73 58.08,73.14 44.62,73.14 43.73,72.25 27.22,72.25 25.32,70.34 25.32,67.8 25.95,67.17 26.54,67.17
LED15: length 133.4
  TOP w0.254: CON9.24 146.6,78.22 v1(146.6,77.71) ; 38.06,67.17 39.92,67.17 42.46,69.71 56.43,69.71 66.59,59.55 144.19,59.55 v1(146.6,61.96)
  BOTTOM w0.254: v1(146.6,61.96) v1(146.6,77.71)
LED16: length 141.9
  TOP w0.254: Q27.2 36.11,67.17 35.47,67.8 35.47,69.08 37.38,70.98 57.7,70.98 67.22,61.45 143.93,61.45 151.3,68.82 162.6,68.82 164.25,70.47 164.25,70.85 CON10.1
LED17: length 128.5
  TOP w0.254: v1(149.27,57.14) 62.65,57.14 52.62,67.17 Q30.5 ; CON10.13 v1(162.86,70.73)
  CONDUCTIVE2 w0.254: v1(162.86,70.73) 162.86,67.55 152.44,57.14 v1(149.27,57.14)
LED18: length 135.3
  TOP w0.254: 166.67,71.36 165.9,69.71 165.9,66.92 157.27,58.28 64.05,58.28 53.25,69.08 46.27,69.08 45.64,68.44 45.64,67.8 46.27,67.17 46.86,67.17
LED19: length 140.3
  TOP w0.254: v1(140.12,80.76) CON9.8 ; v1(121.84,93.2) 121.84,94.47 112.94,103.36 41.83,103.36 37.38,98.92 24.04,98.92 23.41,98.28 23.41,91.93 22.77,91.3 Q34.5
  BOTTOM w0.254: v1(121.84,93.2) 134.28,80.76 v1(140.12,80.76)
LED20: length 142.6
  TOP w0.254: Q34.2 19.6,91.3 18.96,91.93 18.96,98.28 20.23,99.55 36.75,99.55 41.19,104 113.33,104 v1(124.12,93.2) ; CON9.20 v1(139.49,81.9)
  BOTTOM w0.254: v1(124.12,93.2) 124.12,92.19 134.41,81.9 v1(139.49,81.9)
LED21: length 130.2
  TOP w0.254: v1(142.28,79.74) 142.28,80.63 CON9.9 ; v1(119.93,93.84) 111.67,102.09 43.09,102.09 38.65,97.65 33.57,97.65 32.94,97.02 32.94,91.93 32.3,91.3 Q37.5
  BOTTOM w0.254: v1(142.28,79.74) 134.03,79.74 v1(119.93,93.84)
LED22: length 134.8
  TOP w0.254: CON9.21 143.68,85.97 v1(143.68,86.98) ; v1(119.93,95.11) 112.31,102.73 42.46,102.73 38.02,98.28 29.76,98.28 29.13,97.65 29.13,91.93 29.76,91.3 Q37.2
  CONDUCTIVE3 w0.254: v1(143.68,86.98) 135.55,95.11 v1(119.93,95.11)
LED23: length 132.9
  TOP w0.254: 144.95,81.65 144.31,80.38 144.31,65.77 141.9,63.36 69.13,63.36 53.89,78.6 53.89,81.77 44.36,91.3 Q40.5
LED24: length 144.9
  TOP w0.254: Q40.2 37.38,91.3 36.75,91.93 36.75,93.84 38.02,95.11 41.83,95.11 55.16,81.77 55.16,78.6 69.77,63.99 141.39,63.99 143.42,66.03 143.42,80.76 144.06,82.03
LED25: length 141.5
  TOP w0.254: v1(123.23,101.97) 118.02,107.17 75.48,107.17 60.88,121.78 22.14,121.78 18.33,117.97 Q44.5 ; CON9.16 v1(132.31,85.39)
  BOTTOM w0.254: v1(123.23,101.97) 123.23,99.55 126.66,96.13 126.66,91.05 v1(132.31,85.39)
LED26: length 157.3
  TOP w0.254: v1(139.23,94.09) 129.45,103.87 123.87,103.87 119.93,107.81 76.11,107.81 61.51,122.41 13.89,122.41 11.34,119.88 11.34,118.6 11.98,117.97 Q44.2 ; CON9.5 v1(135.04,84.06)
  BOTTOM w0.254: v1(135.04,84.06) 137.07,86.09 137.07,89.9 139.23,92.06 v1(139.23,94.09)
LED27: length 132.3
  TOP w0.254: v1(137.33,91.68) 133.52,95.49 125.9,95.49 115.48,105.9 74.21,105.9 59.6,120.51 29.76,120.51 27.22,117.97 Q47.5 ; CON9.17 v1(135.93,88.25)
  BOTTOM w0.254: v1(135.93,88.25) 135.93,90.28 v1(137.33,91.68)
LED28: length 139.5
  TOP w0.254: CON9.6 v1(138.73,87.11) ; Q47.2 22.14,117.97 21.5,118.6 21.5,119.88 22.77,121.14 60.24,121.14 74.84,106.54 116.12,106.54 126.28,96.38 134.03,96.38 138.73,91.68 v1(138.73,90.03)
  BOTTOM w0.254: v1(138.73,90.03) v1(138.73,87.11)
LED29: length 118.9
  TOP w0.254: CON9.18 137.58,87.08 137.58,88.89 132.63,93.84 124.76,93.84 113.96,104.63 72.94,104.63 61.51,116.06 38.65,116.06 36.75,117.97 Q50.5
LED30: length 127.8
  TOP w0.254: CON9.7 140.38,85.96 140.38,87.24 132.88,94.73 125.14,94.73 114.6,105.27 73.58,105.27 58.97,119.88 32.3,119.88 31.67,119.24 31.67,118.6 32.3,117.97 Q50.2
LED31: length 136.2
  TOP w0.254: 128.71,89.4 127.93,87.74 126.03,87.74 124.38,89.39 v1(121.84,89.39) ; Q54.5 20.87,144.64 v1(21.5,145.28)
  CONDUCTIVE3 w0.254: v1(21.5,145.28) 30.39,136.39 46.91,136.39 69.77,113.52 v1(99.23,113.52)
  BOTTOM w0.254: v1(121.84,89.39) 118.79,92.44 118.79,96.89 102.15,113.52 v1(99.23,113.52)
LED32: length 136.6
  TOP w0.254: Q54.2 17.7,144.64 v1(17.06,145.28) ; v1(125.77,92.57) 125.77,90.92 126.66,90.03 127.68,90.03
  CONDUCTIVE2 w0.254: v1(100.63,112.25) 101.9,112.25 112.31,101.84 116.5,101.84 v1(125.77,92.57)
  CONDUCTIVE3 w0.254: v1(100.63,112.25) 69.77,112.25 46.27,135.75 26.58,135.75 v1(17.06,145.28)
LED33: length 131.8
  TOP w0.254: v1(132.12,92.95) 132.12,91.81 CON9.2 ; Q57.5 31.03,144.64 v1(31.67,145.28)
  CONDUCTIVE3 w0.254: v1(31.67,145.28) 39.28,137.66 48.17,137.66 69.77,116.06 v1(96.82,116.06)
  BOTTOM w0.254: v1(132.12,92.95) 130.47,94.6 130.47,100.44 127.17,103.75 113.96,103.75 101.64,116.06 v1(96.82,116.06)
LED34: length 128.6
  TOP w0.254: CON9.14 v1(130.47,90.66) ; v1(27.86,145.28) 28.49,144.64 29.08,144.64
  CONDUCTIVE2 w0.254: v1(100.37,114.79) 112.18,102.98 118.15,102.98 v1(130.47,90.66)
  CONDUCTIVE3 w0.254: v1(27.86,145.28) 36.11,137.02 47.54,137.02 69.77,114.79 v1(100.37,114.79)
LED35: length 122.4
  TOP w0.254: 132.32,87.68 v1(133.14,89.39) ; 40.59,144.64 43.6,144.64 v1(44.24,144)
  CONDUCTIVE2 w0.254: v1(95.16,118.6) 98.97,118.6 112.31,105.27 124.88,105.27 133.9,96.25 133.9,90.16 v1(133.14,89.39)
  CONDUCTIVE3 w0.254: v1(44.24,144) 69.64,118.6 v1(95.16,118.6)
LED36: length 121.6
  TOP w0.254: v1(38.02,145.28) 38.65,144.64 Q60.2 ; CON9.15 132.5,90.28 v1(132.5,90.92)
  CONDUCTIVE2 w0.254: v1(132.5,90.92) 119.3,104.13 112.18,104.13 v1(98.97,117.33)
  CONDUCTIVE3 w0.254: v1(98.97,117.33) 69.77,117.33 48.81,138.29 45,138.29 v1(38.02,145.28)
LED37: length 53.1
  TOP w0.254: 181.14,64.5 180.51,63.11 180.51,49.77 166.16,35.42 154.85,35.42 151.04,31.61 Q64.5
LED38: length 57.4
  TOP w0.254: CON10.22 179.62,63.61 179.62,50.02 165.65,36.05 149.14,36.05 147.23,34.15 147.23,32.24 147.87,31.61 Q64.2
LED39: length 44.4
  TOP w0.254: CON10.11 182.29,62.22 182.29,48.88 165.01,31.61 Q67.5
LED40: length 58.9
  TOP w0.254: Q67.2 156.12,31.61 154.85,30.34 152.95,30.34 152.31,30.98 152.31,31.61 155.49,34.78 166.67,34.78 181.4,49.52 181.4,62.73 182.03,63.99
LED41: length 37.7
  TOP w0.254: Q70.5 171.24,31.61 184.19,44.56 184.19,61.2 CON10.12
LED42: length 39.2
  TOP w0.254: Q70.2 168.19,31.61 167.56,32.24 167.56,32.88 168.19,33.52 168.32,33.52 183.18,48.37 183.18,61.84 CON10.24
LED+1: length 86.2
  CONDUCTIVE3 w2.184: 110.41,23.99 110.41,17 114.85,12.56 CON2.2 ; v1(73.58,67.17) 73.58,57.65 96.44,34.78 105.96,34.78 110.41,30.34 110.41,26.53
  vias: v1(72.3,68.44) v1(72.3,67.17) v1(73.58,68.44) v1(74.84,68.44) v1(74.84,67.17) v1(109.77,25.89) v1(109.77,24.62) v1(109.77,23.36) v1(111.04,25.89) v1(111.04,24.62) v1(111.04,23.36)
LED+2: length 67.5
  BOTTOM w2.184: 68.49,73.52 68.49,66.53 76.11,58.91 76.11,25.89 ; CON3.2 81.19,13.83 76.11,18.91 76.11,23.99
  vias: v1(67.86,74.79) v1(67.86,73.52) v1(69.13,74.79) v1(69.13,73.52) v1(75.48,24.62) v1(75.48,23.36) v1(76.75,24.62) v1(76.75,23.36)
LED+3: length 69.5
  CONDUCTIVE2 w2.184: v1(20.23,56.38) 20.23,58.28 36.75,74.79 53.89,74.79 58.97,79.87 62.14,79.87 ; 19.6,55.74 19.6,52.56 27.86,44.31 CON4.2
  vias: v1(18.96,56.38) v1(18.96,55.11) v1(18.96,53.84) v1(20.23,55.11) v1(20.23,53.84) v1(61.51,80.5) v1(61.51,79.23) v1(62.78,80.5) v1(62.78,79.23)
LED+4: length 56
  TOP w2.184: CON5.2 13.25,76.06 13.25,78.6
  BOTTOM w2.184: 56.43,86.22 16.43,86.22 13.89,83.68 13.89,79.23
  vias: v1(12.61,79.23) v1(12.61,77.96) v1(13.89,77.96) v1(55.8,86.85) v1(55.8,85.58) v1(57.06,86.85) v1(57.06,85.58)
LED+5: length 55.4
  BOTTOM w2.184: 50.08,91.93 18.33,91.93 12.61,97.65 CON6.2 6.9,101.46 v1(6.9,109.71)
  vias: v1(6.9,110.98) v1(8.17,110.98) v1(8.17,109.71) v1(49.44,92.57) v1(49.44,91.3) v1(50.72,92.57) v1(50.72,91.3)
LED+6: length 60.7
  CONDUCTIVE2 w2.184: 43.73,98.92 43.73,105.27 36.11,112.89 23.41,112.89 13.25,123.05 13.25,126.86 ; 13.25,126.86 CON7.2 ; 13.25,126.86 13.25,136.39
  vias: v1(12.61,137.66) v1(12.61,136.39) v1(13.89,137.66) v1(13.89,136.39) v1(43.09,98.92) v1(43.09,97.65) v1(44.36,98.92) v1(44.36,97.65)
LED+7: length 87.4
  CONDUCTIVE2 w2.184: v1(142.79,25.89) 142.79,27.8 140.25,30.34 105.96,30.34 91.99,44.31 v1(91.99,47.48) ; 143.42,23.99 143.42,17 147.87,12.56 CON8.2
  vias: v1(91.99,50.02) v1(91.99,48.76) v1(93.26,50.02) v1(93.26,48.76) v1(93.26,47.48) v1(142.79,24.62) v1(142.79,23.36) v1(144.06,25.89) v1(144.06,24.62) v1(144.06,23.36)
LED-1: length 63.3
  CONDUCTIVE3 w2.184: v1(139.62,18.27) 139.62,15.1 137.07,12.56 CON2.1 ; 140.25,67.8 140.25,63.36 141.52,62.09 141.52,31.61 139.62,29.71 139.62,20.82
  vias: v1(138.34,18.27) v1(139.62,69.71) v1(139.62,68.44) v1(139.62,67.17) v1(140.88,69.71) v1(140.88,68.44) v1(140.88,67.17) v1(140.88,18.27)
LED-2: length 110.3
  BOTTOM w2.184: v1(106.59,18.27) 106.59,16.37 104.05,13.83 CON3.1 ; v1(135.17,73.52) 135.17,68.44 141.52,62.09 141.52,31.61 138.34,28.44 107.86,28.44 106.59,27.16 106.59,19.55
  vias: v1(105.33,18.27) v1(107.86,18.27) v1(133.9,74.79) v1(133.9,73.52) v1(135.17,74.79)
LED-3: length 134.4
  CONDUCTIVE2 w2.184: v1(127.55,79.23) 128.19,78.6 128.19,76.06 135.17,69.08 135.17,65.9 122.47,53.2 55.8,53.2 53.89,55.11 50.72,55.11 ; v1(50.72,53.84) 50.72,51.3 41.19,41.77 CON4.1
  vias: v1(49.44,53.84) v1(51.98,53.84) v1(127.55,80.5) v1(128.82,80.5) v1(128.82,79.23)
LED-4: length 112
  TOP w2.184: CON5.1 18.96,69.71 24.04,74.79 43.09,74.79 44.36,76.06 v1(44.36,77.96)
  BOTTOM w2.184: 45,78.6 51.35,78.6 52.62,77.33 86.27,77.33 91.99,83.04 118.66,83.04 121.2,85.58
  vias: v1(43.09,77.96) v1(45.64,77.96) v1(121.84,86.85) v1(121.84,85.58) v1(123.1,86.85) v1(123.1,85.58)
LED-5: length 125.1
  TOP w2.184: CON6.1 11.98,95.11 18.33,101.46 35.47,101.46 36.75,102.73 v1(36.75,104.63)
  CONDUCTIVE3 w2.184: v1(116.12,92.57) 116.12,100.19 106.59,109.71 38.02,109.71 36.75,108.44 36.75,105.9
  vias: v1(35.47,104.63) v1(38.02,104.63) v1(116.12,91.3) v1(117.39,92.57) v1(117.39,91.3)
LED-6: length 118.5
  TOP w2.184: CON7.1 15.79,124.32 19.6,128.13 41.83,128.13 43.09,129.4 v1(43.09,131.31)
  CONDUCTIVE2 w2.184: v1(109.77,98.92) 109.77,101.46 107.23,104 104.69,104 89.45,119.24 77.38,119.24 64.05,132.57 43.73,132.57
  vias: v1(41.83,131.31) v1(44.36,131.31) v1(109.77,97.65) v1(111.04,98.92) v1(111.04,97.65)
LED-7: length 49.4
  CONDUCTIVE2 w2.184: v1(156.12,47.48) 156.12,46.22 172.63,29.71 172.63,19.55 ; CON8.1 169.46,12.56 172.63,15.73 v1(172.63,18.27)
  vias: v1(154.85,50.02) v1(154.85,48.76) v1(154.85,47.48) v1(156.12,50.02) v1(156.12,48.76) v1(171.37,18.27) v1(173.91,18.27)
N_1: length 11.9
  TOP w0.254: 116.8,32.11 116.12,32.11 116.12,29.71 116.75,29.07 R13.2 ; R13.1 R12.1 119.81,26.23 ZD3.A 119.91,24.53 Q5.3
N_2: length 11
  TOP w0.254: R11.1 R10.1 114.73,26.23 ZD2.A 114.83,24.53 Q3.3 ; R11.2 112.73,30.12 113.72,31.11 Q4.3
N_3: length 11
  TOP w0.254: R15.1 R14.1 124.89,26.23 ZD4.A 124.99,24.53 Q6.3 ; Q7.3 123.88,31.11 122.89,30.12 R15.2
N_4: length 11.9
  TOP w0.254: Q8.3 130.07,24.53 ZD5.A 129.97,26.23 R16.1 R17.1 ; R17.2 126.91,29.07 126.28,29.71 126.28,32.11 Q7.6
N_5: length 11
  TOP w0.254: R19.2 133.05,30.12 134.03,31.11 Q10.3 ; Q9.3 135.15,24.53 ZD6.A 135.05,26.23 R18.1 R19.1
N_6: length 11.9
  TOP w0.254: Q10.6 136.44,32.11 136.44,29.71 137.07,29.07 R21.2 ; R21.1 R20.1 140.13,26.23 ZD7.A 140.23,24.53 Q11.3
N_7: length 11
  TOP w0.254: R26.2 79.71,30.12 80.69,31.11 Q14.3 ; Q13.3 81.81,24.53 ZD8.A 81.71,26.23 R25.1 R26.1
N_8: length 11.9
  TOP w0.254: Q15.3 86.89,24.53 ZD9.A 86.79,26.23 R27.1 R28.1 ; R28.2 83.73,29.07 83.1,29.71 83.1,32.11 Q14.6
N_9: length 11
  TOP w0.254: R30.2 89.87,30.12 90.85,31.11 Q17.3 ; Q16.3 91.97,24.53 ZD10.A 91.87,26.23 R29.1 R30.1
N_10: length 11.9
  TOP w0.254: 93.94,32.11 93.26,32.11 93.26,29.71 93.89,29.07 R32.2 ; Q18.3 97.05,24.53 ZD11.A 96.95,26.23 R31.1 R32.1
N_11: length 11
  TOP w0.254: Q19.3 102.13,24.53 ZD12.A 102.03,26.23 R33.1 R34.1 ; R34.2 100.03,30.12 101.02,31.11 102.74,31.11
N_12: length 11.9
  TOP w0.254: R36.2 104.05,29.07 103.42,29.71 103.42,32.11 Q20.6 ; R36.1 R35.1 107.11,26.23 ZD13.A 107.21,24.53 Q21.3
N_13: length 11
  TOP w0.254: R41.1 R40.1 25.83,61.79 ZD14.A 25.93,60.09 Q23.3 ; 26.54,66.67 24.82,66.67 23.83,65.69 R41.2
N_15: length 11.9
  TOP w0.254: Q24.6 27.22,67.67 27.22,65.27 27.86,64.63 R43.2 ; Q25.3 31.01,60.09 ZD15.A 30.91,61.79 R42.1 R43.1
N_16: length 66.8
  CONDUCTIVE3 w2.184: v1(82.47,67.17) 82.47,53.84 98.34,37.96 109.77,37.96 114.22,33.52 114.22,20.18
  vias: v1(81.19,68.44) v1(81.19,67.17) v1(82.47,68.44) v1(83.73,68.44) v1(83.73,67.17) v1(112.94,18.27) v1(114.22,18.27) v1(115.48,18.27)
N_18: length 11
  TOP w0.254: Q27.3 34.97,66.67 33.99,65.69 R45.2 ; Q26.3 36.09,60.09 ZD16.A 35.99,61.79 R44.1 R45.1
N_20: length 64.4
  CONDUCTIVE3 w2.184: v1(95.16,67.17) 95.16,64.63 95.8,63.99 95.8,48.12 102.78,41.13 115.48,41.13 119.3,37.32 119.3,21.11 Q5.1
  vias: v1(93.89,68.44) v1(93.89,67.17) v1(95.16,68.44) v1(96.44,68.44) v1(96.44,67.17) v1(118.02,18.27) v1(119.3,18.27) v1(120.56,18.27)
N_22: length 11.9
  TOP w0.254: Q28.3 41.17,60.09 ZD17.A 41.07,61.79 R46.1 R47.1 ; R47.2 38.02,64.63 37.38,65.27 37.38,67.67 38.06,67.67
N_23: length 59
  CONDUCTIVE3 w2.184: v1(107.23,67.17) 107.23,64.63 106.59,63.99 106.59,48.76 111.04,44.31 117.39,44.31 122.47,39.23 122.47,34.15 124.38,32.24 124.38,19.55
  vias: v1(105.96,68.44) v1(105.96,67.17) v1(107.23,68.44) v1(108.5,68.44) v1(108.5,67.17) v1(123.1,18.27) v1(124.38,18.27) v1(125.65,18.27)
N_25: length 11
  TOP w0.254: R49.1 R48.1 46.15,61.79 ZD18.A 46.25,60.09 Q29.3 ; R49.2 44.15,65.69 45.14,66.67 46.86,66.67
N_26: length 50.8
  CONDUCTIVE3 w2.184: 129.45,20.82 129.45,37.32 118.66,48.12 v1(118.66,67.17)
  vias: v1(117.39,68.44) v1(117.39,67.17) v1(118.66,68.44) v1(119.93,68.44) v1(119.93,67.17) v1(128.19,18.27) v1(129.45,18.27) v1(130.72,18.27)
N_28: length 11.9
  TOP w0.254: Q30.6 47.54,67.67 47.54,65.27 48.17,64.63 R51.2 ; Q31.3 51.33,60.09 ZD19.A 51.23,61.79 R50.1 R51.1
N_29: length 54.9
  BOTTOM w2.184: 81.19,20.18 81.19,62.73 77.38,66.53 v1(77.38,73.52)
  vias: v1(76.11,74.79) v1(76.11,73.52) v1(77.38,74.79) v1(78.66,74.79) v1(78.66,73.52) v1(79.92,18.27) v1(81.19,18.27) v1(82.47,18.27)
N_30: length 49.4
  CONDUCTIVE3 w2.184: v1(131.36,67.17) 131.36,64.63 130.09,63.36 130.09,47.48 134.53,43.04 134.53,20.18
  vias: v1(130.09,68.44) v1(130.09,67.17) v1(131.36,68.44) v1(132.63,68.44) v1(132.63,67.17) v1(133.26,18.27) v1(134.53,18.27) v1(135.81,18.27)
N_32: length 11
  TOP w0.254: Q33.3 19.58,84.21 ZD20.A 19.48,85.92 R55.1 R56.1 ; Q34.3 18.46,90.8 17.48,89.81 R56.2
N_33: length 11.9
  TOP w0.254: Q34.6 20.87,91.8 20.87,89.39 21.5,88.76 R58.2 ; Q35.3 24.66,84.21 ZD21.A 24.56,85.92 R57.1 R58.1
N_35: length 11
  TOP w0.254: Q36.3 29.74,84.21 ZD22.A 29.64,85.92 R59.1 R60.1 ; R60.2 27.64,89.81 28.63,90.8 Q37.3
N_36: length 11.9
  TOP w0.254: R62.1 R61.1 34.72,85.92 ZD23.A 34.82,84.21 Q38.3 ; R62.2 31.67,88.76 31.03,89.39 31.03,91.8 Q37.6
N_38: length 11
  TOP w0.254: Q39.3 39.9,84.21 ZD24.A 39.8,85.92 R63.1 R64.1 ; R64.2 37.8,89.81 38.78,90.8 Q40.3
N_39: length 54.7
  BOTTOM w2.184: v1(89.45,73.52) 89.45,66.53 86.27,63.36 86.27,20.18
  vias: v1(85,18.27) v1(86.27,18.27) v1(87.55,18.27) v1(88.18,74.79) v1(88.18,73.52) v1(89.45,74.79) v1(90.72,74.79) v1(90.72,73.52)
N_41: length 11.9
  TOP w0.254: Q40.6 41.19,91.8 41.19,89.39 41.83,88.76 R66.2 ; Q41.3 44.98,84.21 ZD25.A 44.88,85.92 R65.1 R66.1
N_42: length 61.8
  BOTTOM w2.184: 91.35,20.18 91.35,29.07 106.59,44.31 106.59,62.09 101.52,67.17 v1(101.52,73.52)
  vias: v1(90.08,18.27) v1(91.35,18.27) v1(92.62,18.27) v1(100.24,74.79) v1(100.24,73.52) v1(101.52,74.79) v1(102.78,74.79) v1(102.78,73.52)
N_44: length 11
  TOP w0.254: Q43.3 11.96,110.88 ZD26.A 11.86,112.59 R70.1 R71.1 ; Q44.3 10.84,117.47 9.86,116.48 R71.2
N_45: length 72.1
  BOTTOM w2.184: v1(113.58,73.52) 113.58,67.17 118.66,62.09 118.66,37.96 115.48,34.78 102.78,34.78 96.44,28.44 96.44,20.18
  vias: v1(95.16,18.27) v1(96.44,18.27) v1(97.7,18.27) v1(112.31,74.79) v1(112.31,73.52) v1(113.58,74.79) v1(114.85,74.79) v1(114.85,73.52)
N_47: length 11.9
  TOP w0.254: Q44.6 13.25,118.47 13.25,116.06 13.89,115.43 R73.2 ; R73.1 R72.1 16.94,112.59 ZD27.A 17.04,110.88 Q45.3
N_48: length 79.6
  BOTTOM w2.184: v1(125.01,73.52) 125.01,67.8 130.09,62.73 130.09,34.78 126.91,31.61 105.96,31.61 101.52,27.16 101.52,20.18
  vias: v1(100.24,18.27) v1(101.52,18.27) v1(102.78,18.27) v1(123.74,74.79) v1(123.74,73.52) v1(125.01,74.79) v1(126.28,74.79) v1(126.28,73.52)
N_50: length 11
  TOP w0.254: R75.1 R74.1 22.02,112.59 ZD28.A 22.12,110.88 Q46.3 ; Q47.3 21,117.47 20.02,116.48 R75.2
N_51: length 11.9
  TOP w0.254: Q48.3 27.2,110.88 ZD29.A 27.1,112.59 R76.1 R77.1 ; Q47.6 23.41,118.47 23.41,116.06 24.04,115.43 R77.2
N_53: length 11
  TOP w0.254: Q49.3 32.28,110.88 ZD30.A 32.18,112.59 R78.1 R79.1 ; R79.2 30.18,116.48 31.17,117.47 Q50.3
N_54: length 11.9
  TOP w0.254: Q50.6 33.57,118.47 33.57,116.06 34.2,115.43 R81.2 ; Q51.3 37.36,110.88 ZD31.A 37.26,112.59 R80.1 R81.1
N_55: length 11
  TOP w0.254: Q54.3 17.2,144.14 16.21,143.16 R86.2 ; Q53.3 18.31,137.56 ZD32.A 18.21,139.26 R85.1 R86.1
N_57: length 58.1
  CONDUCTIVE2 w2.184: v1(71.03,79.23) 71.03,77.33 70.4,76.69 65.95,76.69 60.88,71.61 38.65,71.61 25.32,58.28 25.32,55.74
  vias: v1(24.04,53.84) v1(25.32,53.84) v1(26.58,53.84) v1(69.77,80.5) v1(69.77,79.23) v1(71.03,80.5) v1(72.3,80.5) v1(72.3,79.23)
N_59: length 11.9
  TOP w0.254: Q54.6 19.6,145.14 19.6,142.74 20.23,142.1 R88.2 ; R88.1 R87.1 23.29,139.26 ZD33.A 23.39,137.56 Q55.3
N_60: length 67.3
  CONDUCTIVE2 w2.184: v1(83.1,79.23) 83.1,74.15 79.92,70.98 71.67,70.98 69.13,68.44 39.92,68.44 30.39,58.91 30.39,55.74
  vias: v1(29.13,53.84) v1(30.39,53.84) v1(31.67,53.84) v1(81.83,80.5) v1(81.83,79.23) v1(83.1,80.5) v1(84.37,80.5) v1(84.37,79.23)
N_62: length 11
  TOP w0.254: 29.08,144.14 27.36,144.14 26.37,143.16 R90.2 ; Q56.3 28.47,137.56 ZD34.A 28.37,139.26 R89.1 R90.1
N_63: length 89.7
  CONDUCTIVE2 w2.184: 34.84,55.74 35.47,56.38 35.47,58.28 42.46,65.27 58.97,65.27 61.51,62.73 97.7,62.73 101.52,66.53 101.52,69.08 95.16,75.42 v1(95.16,79.23)
  vias: v1(34.2,53.84) v1(35.47,53.84) v1(36.75,53.84) v1(93.89,80.5) v1(93.89,79.23) v1(95.16,80.5) v1(96.44,80.5) v1(96.44,79.23)
N_65: length 11.9
  TOP w0.254: Q58.3 33.55,137.56 ZD35.A 33.45,139.26 R91.1 R92.1 ; Q57.6 29.76,145.14 29.76,142.74 30.39,142.1 R92.2
N_66: length 96.4
  CONDUCTIVE2 w2.184: 40.56,55.74 40.56,58.28 44.36,62.09 57.06,62.09 59.6,59.55 106.59,59.55 113.58,66.53 113.58,69.08 107.23,75.42 v1(107.23,79.23)
  vias: v1(39.28,53.84) v1(40.56,53.84) v1(41.83,53.84) v1(105.96,80.5) v1(105.96,79.23) v1(107.23,80.5) v1(108.5,80.5) v1(108.5,79.23)
N_68: length 11
  TOP w0.254: R94.2 36.53,143.16 37.52,144.14 Q60.3 ; R94.1 R93.1 38.53,139.26 ZD36.A 38.63,137.56 Q59.3
N_69: length 102.4
  CONDUCTIVE2 w2.184: 45.64,55.11 45.64,57.65 46.91,58.91 55.16,58.91 57.7,56.38 114.22,56.38 125.01,67.17 125.01,69.08 119.3,74.79 v1(119.3,79.23)
  vias: v1(44.36,53.84) v1(45.64,53.84) v1(46.91,53.84) v1(118.02,80.5) v1(118.02,79.23) v1(119.3,80.5) v1(120.56,80.5) v1(120.56,79.23)
N_71: length 11.9
  TOP w0.254: R96.2 40.56,142.1 39.92,142.74 39.92,145.14 40.59,145.14 ; R96.1 R95.1 43.61,139.26 ZD37.A 43.71,137.56 Q61.3
N_72: length 11
  TOP w0.254: Q63.3 147.85,24.53 ZD38.A 147.75,26.23 R100.1 R101.1 ; R101.2 145.75,30.12 146.73,31.11 Q64.3
N_74: length 11.9
  TOP w0.254: Q64.6 149.14,32.11 149.14,29.71 149.78,29.07 R103.2 ; R103.1 R102.1 152.83,26.23 ZD39.A 152.93,24.53 Q65.3
N_75: length 11
  TOP w0.254: Q66.3 158.01,24.53 ZD40.A 157.91,26.23 R104.1 R105.1 ; Q67.3 156.9,31.11 155.91,30.12 R105.2
N_76: length 11.5
  TOP w0.254: R107.2 160.57,29.07 159.3,30.34 159.3,32.11 Q67.6 ; R107.1 R106.1 162.99,26.23 ZD41.A 163.09,24.53 Q68.3
N_77: length 11
  TOP w0.254: R109.1 R108.1 168.07,26.23 ZD42.A 168.17,24.53 Q69.3 ; Q70.3 167.06,31.11 166.07,30.12 R109.2
N_78: length 49.8
  CONDUCTIVE3 w2.184: 18.96,78.6 18.96,82.41 25.32,88.76 59.6,88.76 61.51,86.85
  vias: v1(17.7,77.96) v1(18.96,77.96) v1(20.23,77.96) v1(64.05,86.85) v1(64.05,85.58) v1(65.32,86.85) v1(65.32,85.58) v1(66.59,86.85) v1(66.59,85.58)
N_80: length 11.9
  TOP w0.254: Q70.6 169.46,32.11 169.46,29.71 170.09,29.07 R111.2 ; R111.1 R110.1 173.15,26.23 ZD43.A 173.25,24.53 Q71.3
N_81: length 57.5
  CONDUCTIVE2 w2.184: 24.04,79.87 24.04,84.31 28.49,88.76 71.67,88.76 74.21,86.22
  vias: v1(22.77,77.96) v1(24.04,77.96) v1(25.32,77.96) v1(76.11,86.85) v1(76.11,85.58) v1(77.38,86.85) v1(77.38,85.58) v1(78.66,86.85) v1(78.66,85.58)
N_84: length 58.5
  BOTTOM w2.184: 85,85.58 81.83,82.41 32.3,82.41 29.13,79.23
  vias: v1(27.86,77.96) v1(29.13,77.96) v1(30.39,77.96) v1(88.18,86.85) v1(88.18,85.58) v1(89.45,86.85) v1(89.45,85.58) v1(90.72,86.85) v1(90.72,85.58)
N_87: length 73.8
  CONDUCTIVE3 w2.184: v1(101.52,85.58) 101.52,83.68 100.24,82.41 51.35,82.41 50.08,83.68 35.47,83.68 34.2,81.77 34.2,79.23
  vias: v1(32.94,77.96) v1(34.2,77.96) v1(35.47,77.96) v1(100.24,86.85) v1(100.24,85.58) v1(101.52,86.85) v1(102.78,86.85) v1(102.78,85.58)
N_90: length 85.2
  CONDUCTIVE3 w2.184: 39.28,79.23 v1(39.28,77.96) 39.28,76.69 41.19,74.79 53.89,74.79 55.8,76.69 110.41,76.69 112.94,79.23 v1(112.94,85.58)
  vias: v1(38.02,77.96) v1(40.56,77.96) v1(111.67,86.85) v1(111.67,85.58) v1(112.94,86.85) v1(114.22,86.85) v1(114.22,85.58)
N_99: length 62.1
  BOTTOM w2.184: v1(11.34,104.63) 11.34,103.36 12.61,102.09 39.92,102.09 43.73,105.9 55.16,105.9 58.97,102.09 v1(58.97,92.57)
  vias: v1(10.07,104.63) v1(12.61,104.63) v1(57.7,92.57) v1(57.7,91.3) v1(58.97,91.3) v1(60.24,92.57) v1(60.24,91.3)
N_102: length 68.6
  BOTTOM w2.184: v1(71.03,92.57) 71.03,100.19 61.51,109.71 17.7,109.71 16.43,108.44 16.43,106.54
  vias: v1(15.16,104.63) v1(16.43,104.63) v1(17.7,104.63) v1(69.77,92.57) v1(69.77,91.3) v1(71.03,91.3) v1(72.3,92.57) v1(72.3,91.3)
N_105: length 82.9
  CONDUCTIVE3 w2.184: 21.5,106.54 21.5,109.71 25.95,114.16 v1(57.7,114.16) v1(58.97,114.16) v1(60.24,114.16)
  BOTTOM w2.184: v1(57.7,114.16) v1(58.97,114.16) v1(60.24,114.16) 69.77,114.16 83.1,100.82 v1(83.1,92.57)
  vias: v1(20.23,104.63) v1(21.5,104.63) v1(22.77,104.63) v1(81.83,92.57) v1(81.83,91.3) v1(83.1,91.3) v1(84.37,92.57) v1(84.37,91.3)
N_108: length 71.5
  CONDUCTIVE3 w2.184: 91.99,92.57 89.45,95.11 40.56,95.11 36.75,98.92 30.39,98.92 26.58,102.73 v1(26.58,104.63)
  vias: v1(25.32,104.63) v1(27.86,104.63) v1(93.89,92.57) v1(93.89,91.3) v1(95.16,92.57) v1(95.16,91.3) v1(96.44,92.57) v1(96.44,91.3)
N_111: length 90
  CONDUCTIVE3 w2.184: v1(107.23,92.57) 107.23,101.46 102.78,105.9 43.73,105.9 39.92,102.09 32.3,102.09 31.67,102.73 v1(31.67,104.63)
  vias: v1(30.39,104.63) v1(32.94,104.63) v1(105.96,92.57) v1(105.96,91.3) v1(107.23,91.3) v1(108.5,92.57) v1(108.5,91.3)
N_120: length 52
  CONDUCTIVE2 w2.184: v1(53.25,98.92) 53.25,101.46 38.65,116.06 30.39,116.06 17.7,128.77 v1(17.7,131.31)
  vias: v1(16.43,131.31) v1(18.96,131.31) v1(51.98,98.92) v1(51.98,97.65) v1(53.25,97.65) v1(54.53,98.92) v1(54.53,97.65)
N_123: length 58.9
  CONDUCTIVE2 w2.184: v1(65.32,98.92) 65.32,101.46 47.54,119.24 32.3,119.24 22.77,128.77 v1(22.77,131.31)
  vias: v1(21.5,131.31) v1(24.04,131.31) v1(64.05,98.92) v1(64.05,97.65) v1(65.32,97.65) v1(66.59,98.92) v1(66.59,97.65)
N_126: length 65.5
  CONDUCTIVE2 w2.184: v1(27.86,131.31) 27.86,129.4 34.84,122.41 56.43,122.41 77.38,101.46 v1(77.38,98.92)
  vias: v1(26.58,131.31) v1(29.13,131.31) v1(76.11,98.92) v1(76.11,97.65) v1(77.38,97.65) v1(78.66,98.92) v1(78.66,97.65)
N_129: length 72.5
  CONDUCTIVE2 w2.184: v1(32.94,131.31) 32.94,129.4 36.75,125.59 60.88,125.59 73.58,112.89 78.02,112.89 89.45,101.46 v1(89.45,98.92)
  vias: v1(31.67,131.31) v1(34.2,131.31) v1(88.18,98.92) v1(88.18,97.65) v1(89.45,97.65) v1(90.72,98.92) v1(90.72,97.65)
N_132: length 79.1
  CONDUCTIVE2 w2.184: v1(101.52,98.92) 101.52,101.46 86.91,116.06 75.48,116.06 62.78,128.77 39.28,128.77 38.02,130.03 v1(38.02,131.31)
  vias: v1(36.75,131.31) v1(39.28,131.31) v1(100.24,98.92) v1(100.24,97.65) v1(101.52,97.65) v1(102.78,98.92) v1(102.78,97.65)
N_141: length 69.2
  CONDUCTIVE2 w2.184: 147.87,18.91 147.87,29.71 144.06,33.52 107.86,33.52 100.88,40.5 v1(100.88,47.48)
  vias: v1(99.61,48.76) v1(99.61,47.48) v1(100.88,48.76) v1(102.15,48.76) v1(102.15,47.48) v1(145.97,18.27) v1(147.23,18.27) v1(148.5,18.27)
N_144: length 58.4
  CONDUCTIVE2 w2.184: v1(112.94,47.48) 112.94,44.95 114.85,43.04 121.2,43.04 127.55,36.69 145.33,36.69 152.31,29.71 152.31,19.55
  vias: v1(111.67,48.76) v1(111.67,47.48) v1(112.94,48.76) v1(114.22,48.76) v1(114.22,47.48) v1(151.04,18.27) v1(152.31,18.27) v1(153.59,18.27)
N_147: length 51.5
  CONDUCTIVE2 w2.184: v1(124.38,47.48) 124.38,45.58 130.09,39.87 148.5,39.87 156.76,31.61 156.76,20.18
  vias: v1(123.1,48.76) v1(123.1,47.48) v1(124.38,48.76) v1(125.65,48.76) v1(125.65,47.48) v1(156.12,18.27) v1(157.4,18.27) v1(158.66,18.27)
N_150: length 45.4
  CONDUCTIVE2 w2.184: v1(135.81,47.48) 135.81,44.95 137.71,43.04 149.78,43.04 162.47,30.34 162.47,20.18
  vias: v1(134.53,48.76) v1(134.53,47.48) v1(135.81,48.76) v1(137.07,48.76) v1(137.07,47.48) v1(161.2,18.27) v1(162.47,18.27) v1(163.75,18.27)
N_153: length 33.1
  CONDUCTIVE2 w2.184: 150.41,46.85 167.56,29.71 167.56,20.82
  vias: v1(145.97,48.76) v1(145.97,47.48) v1(147.23,48.76) v1(147.23,47.48) v1(148.5,48.76) v1(148.5,47.48) v1(166.28,18.27) v1(167.56,18.27) v1(168.82,18.27)

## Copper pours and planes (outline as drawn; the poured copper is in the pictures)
GND on TOP: 144.61,64.35 144.54,64.4 144.56,64.48 148.19,68.12 148.25,68.21 148.27,68.31 148.27,77.86 148.28,77.9 148.47,78.27 148.51,78.3 148.73,78.33 148.86,78.46 149.89,80.62 149.93,80.66 149.99,80.66 163.64,74.2 163.68,74.16 163.68,74.1 162.67,71.99 162.64,71.85 162.69,71.71 162.8,71.62 162.88,71.58 162.92,71.54 162.92,71.48 162.78,71.2 162.76,71.17 162.73,71.16 162.66,70.32 163.27,70.89 163.27,70.93 163.28,70.96 163.42,71.25 163.46,71.28 163.52,71.28 163.61,71.23 163.7,71.21 163.78,71.21 163.84,71.2 163.87,71.14 163.87,70.51 163.87,70.49 163.85,70.46 162.54,69.15 162.51,69.13 162.48,69.12 151.22,69.12 151.16,69.06 151.1,69.02 146.46,64.37 146.44,64.36 146.41,64.35 145.37,64.35 145.35,64.36 145.33,64.37 145.08,64.45 144.82,64.37 144.8,64.36 144.78,64.35
GND on TOP: 142.11,63 142.04,63.05 142.07,63.14 142.1,63.16 144.51,65.58 144.57,65.67 144.59,65.77 144.59,78.27 144.64,78.34 144.72,78.32 145.38,78.27 145.38,78.93 145.36,78.96 145.35,78.99 145.35,79.53 145.36,79.57 145.43,79.71 145.47,79.75 145.7,79.77 145.84,79.9 146.39,81.06 146.43,81.1 146.49,81.09 147.17,80.77 147.2,80.73 147.2,80.67 146.65,79.51 146.63,79.34 146.73,79.15 146.73,79.1 146.35,78.34 146.33,78.28 146.32,78.22 146.32,78.1 146.32,78.07 146.3,78.04 146.6,77.26 146.9,78.04 146.88,78.07 146.88,78.1 146.88,78.17 147.22,78.85 147.26,78.89 147.31,78.89 147.39,78.88 147.46,78.89 147.51,78.89 147.55,78.85 147.6,78.77 147.68,78.71 147.71,78.7 147.75,78.66 147.75,78.6 147.73,78.54 147.72,78.47 147.72,68.46 147.71,68.43 147.7,68.41 142.32,63.02 142.29,63.01 142.26,63
GND on TOP: outline of 107 points within 35.75,58.56 166.2,72.03
GND on TOP: 153.1,30.62 153.07,30.62 153.04,30.64 152.61,31.07 152.6,31.09 152.59,31.12 152.59,31.46 152.6,31.49 152.61,31.52 155.58,34.49 155.61,34.5 155.64,34.51 167.09,34.51 167.14,34.49 167.16,34.43 167.16,34.18 167.16,34.15 167.14,34.13 164.92,31.91 164.9,31.89 164.87,31.89 160.47,31.89 160.41,31.91 160.39,31.98 160.4,32.03 160.4,32.19 160.32,32.38 160.12,32.46 159.82,32.46 159.74,32.45 159.64,32.39 159.61,32.39 159.3,32.39 159.26,32.38 159.19,32.37 159.17,32.37 158.28,32.37 158.28,31.96 158.26,31.91 158.21,31.89 156.12,31.89 156.07,31.88 155.99,31.86 154.76,30.64 154.74,30.62 154.71,30.62
GND on TOP: 160.19,82.19 160.15,82.23 160.16,82.29 160.3,82.58 162.06,86.28 162.1,86.32 162.16,86.32 166.34,84.35 166.38,84.3 166.38,84.25 164.65,80.57 164.61,80.48 164.48,80.19 164.43,80.15 164.38,80.16
